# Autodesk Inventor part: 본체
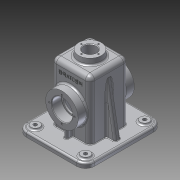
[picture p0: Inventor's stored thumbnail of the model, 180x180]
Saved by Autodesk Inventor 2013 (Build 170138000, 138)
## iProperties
Created: 2016-01
Part Number: 본체
Material: 알루미늄 6061
Document SubType Name: Modeling
Designer: User
Density: 2.71 g/cm^3
Mass: 804.864 g
Surface Area: 910.184 cm^2
Volume: 296.998 cm^3
Author: User
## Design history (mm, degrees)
sketch "스케치1"
  geometry: L1 (-32.5, -55)-(32.5, -55); L2 (32.5, -55)-(32.5, 55); L3 (32.5, 55)-(-32.5, 55); L4 (-32.5, 55)-(-32.5, -55); L5 (-32.5, -55)-(32.5, 55); L6 (32.5, -55)-(-32.5, 55); 1 further point
  constraints: 12 end point, 2 midpoint, 2 parallel, 1 horizontal, 1 perpendicular
  dimensions: "d0" = 65 distance of L2.end L3.end; "d2" = 110 distance of L1.end L2.end
extrude "돌출1" new body sketch "스케치1" stored distance "d3" = 65; taper "d4" = 0 deg
feature "쉘1" dims "d5" = 5
sketch "스케치2"
  geometry: L1 (-32.5, -55)-(-32.5, 55) reference; L2 (-32.5, 55)-(32.5, 55) reference; L3 (32.5, 55)-(32.5, -55) reference; L4 (32.5, -55)-(27.5, -55) reference; L5 (27.5, -55)-(27.5, 50) reference; L6 (27.5, 50)-(-27.5, 50) reference; L7 (-27.5, 50)-(-27.5, -55) reference; L8 (-27.5, -55)-(-32.5, -55) reference; L9 (32.5, 27.5)-(47.5, 27.5); L10 (47.5, 27.5)-(47.5, 0); L11 (75.884, 0)-(-75.884, 0); L12 (32.5, 27.5)-(32.5, 0); L13 (32.5, 0)-(47.5, 0); 2 further points
  constraints: 10 end point, 3 perpendicular, 2 midpoint, 2 point on line, 1 coincident, 1 parallel
  dimensions: "d6" = 55 diameter of L9 L11; "d8" = 15 distance of L9.start L9.end
revolve "회전1" sketch "스케치2" stored, may be unused: angle "d9" = 90 deg
hole "구멍1" diameter "d12" = 30; stored, may be unused: countersink angle "d16" = 90 deg, drill point angle "d18" = 118 deg; dims "d10" = 10, "d11" = 10, "d13" = 6, "d14" = 35, "d15" = 17, "d17" = 8
sketch "스케치3"
  geometry: L1 (84.363, 0)-(-84.363, 0); L2 (65, 20)-(55, 20); L3 (55, 20)-(55, 0); L4 (55, 0)-(65, 0); L5 (65, 0)-(65, 20); L6 (65, 20)-(55, 0); L7 (55, 20)-(65, 0); L8 (55, -32.5)-(-55, -32.5) reference; L9 (-55, -32.5)-(-55, -27.5) reference; L10 (-55, -27.5)-(50, -27.5) reference; L11 (50, -27.5)-(50, 27.5) reference; L12 (50, 27.5)-(-55, 27.5) reference; L13 (-55, 27.5)-(-55, 32.5) reference; L14 (-55, 32.5)-(55, 32.5) reference; L15 (55, 32.5)-(55, -32.5) reference; 3 further points
  constraints: 14 end point, 3 midpoint, 2 horizontal, 2 parallel, 1 coincident, 1 perpendicular, 1 point on line
  dimensions: "d19" = 40 diameter of L2 L1; "d21" = 10 distance between parallel lines of L15 L5; "d22" = 10 distance of L3.end L4.end
revolve "회전2" sketch "스케치3" stored, may be unused: angle "d23" = 90 deg
hole "구멍2" diameter "d26" = 21; stored, may be unused: countersink angle "d30" = 90 deg, drill point angle "d32" = 118 deg; dims "d24" = 10, "d25" = 10, "d27" = 6, "d28" = 4, "d29" = 2, "d31" = 8
sketch "스케치4"
  geometry: L1 (65, -65)-(65, 0) reference; L2 (0, 0)-(65, 0) reference; L3 (0, 0)-(0, -65) reference; L4 (65, -65)-(0, -65) reference; L5 (-27.5, -85)-(92.5, -85); L6 (92.5, -85)-(92.5, 20); L7 (92.5, 20)-(-27.5, 20); L8 (-27.5, 20)-(-27.5, -85); L9 (-27.5, -85)-(92.5, 20); L10 (92.5, -85)-(-27.5, 20); L11 (5, -60)-(60, -60); L12 (60, -60)-(60, -5); L13 (60, -5)-(5, -5); L14 (5, -5)-(5, -60); L15 (5, -60)-(60, -5); L16 (60, -60)-(5, -5); 1 further point
  constraints: 24 end point, 4 midpoint, 4 parallel, 2 horizontal, 2 perpendicular
  dimensions: "d33" = 120 distance of L6.end L7.end; "d35" = 105 distance of L5.end L6.end
extrude "돌출2" join sketch "스케치4" distance "d36" = 2; taper "d37" = 0 deg
sketch "스케치5"
  geometry: L1 (-32.5, -25)-(97.5, -25); L2 (97.5, -25)-(97.5, 90); L3 (97.5, 90)-(-32.5, 90); L4 (-32.5, 90)-(-32.5, -25); L5 (-32.5, -25)-(97.5, 90); L6 (97.5, -25)-(-32.5, 90); L7 (0, 0)-(65, 0); L8 (65, 0)-(65, 65); L9 (65, 65)-(0, 65); L10 (0, 65)-(0, 0); L11 (0, 0)-(65, 65); L12 (65, 0)-(0, 65); 1 further point
  constraints: 24 end point, 4 midpoint, 4 parallel, 2 horizontal, 2 perpendicular
  dimensions: "d38" = 130 distance of L3.end L2.end; "d39" = 115 distance of L2.end L1.end
extrude "돌출3" join sketch "스케치5" distance "d40" = 8; taper "d41" = 0 deg
sketch "스케치6"
  geometry: L1 (-42.5, -27.5)-(-42.5, -45); L2 (-27.5, 15)-(-30.5, 15) reference; L3 (-30.5, 15)-(-30.5, 17.5) reference; L4 (-30.5, 17.5)-(-47.5, 17.5) reference; L5 (-47.5, 17.5)-(-47.5, 27.5) reference; L6 (-47.5, 27.5)-(-32.5, 27.5) reference; L7 (-32.5, 27.5)-(-32.5, 55) reference; L8 (-32.5, 55)-(-20, 55) reference; L9 (-20, 55)-(-20, 65) reference; L10 (-20, 65)-(-10.5, 65) reference; L11 (-10.5, 65)-(-10.5, 50) reference; L12 (-10.5, 50)-(-27.5, 50) reference; L13 (-27.5, 50)-(-27.5, 15) reference; L14 (-30.5, -15)-(-27.5, -15) reference; L15 (-27.5, -15)-(-27.5, -55) reference; L16 (-27.5, -55)-(-60, -55) reference; L17 (-60, -55)-(-60, -53) reference; L18 (-60, -53)-(-65, -53) reference; L19 (-65, -53)-(-65, -45) reference; L20 (-65, -45)-(-32.5, -45) reference; L21 (-32.5, -45)-(-32.5, -27.5) reference; L22 (-32.5, -27.5)-(-47.5, -27.5) reference; L23 (-47.5, -27.5)-(-47.5, -17.5) reference; L24 (-47.5, -17.5)-(-30.5, -17.5) reference; L25 (-30.5, -17.5)-(-30.5, -15) reference; L26 (30.5, 15)-(27.5, 15) reference; L27 (27.5, 15)-(27.5, 50) reference; L28 (27.5, 50)-(10.5, 50) reference; L29 (10.5, 50)-(10.5, 65) reference; L30 (10.5, 65)-(20, 65) reference; L31 (20, 65)-(20, 55) reference; L32 (20, 55)-(32.5, 55) reference; L33 (32.5, 55)-(32.5, 27.5) reference; L34 (32.5, 27.5)-(47.5, 27.5) reference; L35 (47.5, 27.5)-(47.5, 17.5) reference; L36 (47.5, 17.5)-(30.5, 17.5) reference; L37 (30.5, 17.5)-(30.5, 15) reference; L38 (27.5, -15)-(30.5, -15) reference; L39 (30.5, -15)-(30.5, -17.5) reference; L40 (30.5, -17.5)-(47.5, -17.5) reference; L41 (47.5, -17.5)-(47.5, -27.5) reference; L42 (47.5, -27.5)-(32.5, -27.5) reference; L43 (32.5, -27.5)-(32.5, -45) reference; L44 (32.5, -45)-(65, -45) reference; L45 (65, -45)-(65, -53) reference; L46 (65, -53)-(60, -53) reference; L47 (60, -53)-(60, -55) reference; L48 (60, -55)-(27.5, -55) reference; L49 (27.5, -55)-(27.5, -15) reference; 1 further point
  constraints: 2 end point, 2 point on line, 1 parallel, 1 vertical
  dimensions: "d42" = 15 distance between parallel lines of L1 L15
feature "리브1" sketch "스케치6" dims "d43" = 1, "d44" = 6, "d45" = 0, "d46" = 0, "d47" = 1, "d48" = 1
sketch "스케치7"
  geometry: L1 (40.069, -32.5)-(-45, -47.5); L2 (-53, -57.5)-(-45, -57.5) reference; L3 (-45, -57.5)-(-45, 57.5) reference; L4 (-45, -32.5)-(55, -32.5) reference; 1 further point
  constraints: 2 end point, 2 point on line
  dimensions: "d49" = 10 distance from line of L2 L1.end; "d50" = 10 deg angle of L2 L1
feature "리브2" sketch "스케치7" dims "d51" = 1, "d52" = 10, "d53" = 0, "d54" = 0, "d55" = 1, "d56" = 1
sketch "스케치8"
  geometry: C1 r 7.5 at (-17.5, 75); 1 further point
  constraints: 1 centre point
  dimensions: "d57" = 15 diameter of C1; "d58" = 50 horizontal distance of point (32.5, 32.5) C1.centre; "d59" = 42.5 vertical distance of point (32.5, 32.5) C1.centre
extrude "돌출4" join sketch "스케치8" distance "d60" = 3; taper "d61" = 0 deg
sketch "스케치9"
  geometry: C1 r 7.5 at (0, 0) reference; C2 r 3 at (0, 0); 1 further point
  constraints: 1 centre point, 1 coincident
  dimensions: "d62" = 6 diameter of C2
extrude "돌출5" cut sketch "스케치9" distance "d64" = 40; taper "d65" = 0 deg
fillet "모깎기1" dims "d66" = 10
fillet "모깎기2" dims "d67" = 15
fillet "모깎기3" dims "d68" = 3
fillet "모깎기4" dims "d75" = 8
fillet "모깎기5" dims "d76" = 8
sketch "스케치10"
  geometry: C1 r 20 at (0, 0) reference; 1 further point
  constraints: 1 vertical alignment
  dimensions: "d77" = 14.5 distance of C1.centre point (0, 14.5)
hole "구멍3" sketch "스케치10" at (0, 14.5) diameter "d78" = 2.459; stored, may be unused: countersink angle "d82" = 90 deg, drill point angle "d84" = 118 deg; dims "d79" = 7, "d80" = 3.6, "d81" = 2, "d83" = 9
sketch "스케치11"
  geometry: C1 r 17.5 at (0, 0) reference; 1 further point
  constraints: 1 vertical alignment
  dimensions: "d88" = 21 distance of C1.centre point (0, 21)
hole "구멍4" sketch "스케치11" at (0, 21) diameter "d89" = 3.242; stored, may be unused: countersink angle "d93" = 90 deg, drill point angle "d95" = 118 deg; dims "d90" = 8, "d91" = 3.6, "d92" = 2, "d94" = 10
fillet "모깎기6" dims "d99" = 3
fillet "모깎기7" dims "d100" = 3
fillet "모깎기8" dims "d101" = 3
fillet "모깎기9" dims "d102" = 3
fillet "모깎기10" dims "d103" = 3
fillet "모깎기11" dims "d104" = 3
fillet "모깎기12" dims "d105" = 3
fillet "모깎기13" dims "d106" = 3
fillet "모깎기14" dims "d107" = 1
fillet "모깎기15" dims "d108" = 3
fillet "모깎기16" dims "d109" = 3
chamfer "모따기1" distance "d110" = 1; stored, may be unused: second distance "d111" = 2, angle "d112" = 45 deg
fillet "모깎기17" dims "d113" = 0.3
chamfer "모따기2" distance "d114" = 1; stored, may be unused: second distance "d115" = 2, angle "d116" = 45 deg
sketch "스케치12"
  geometry: L1 (44.5, 18)-(4.5, 18) reference; L2 (-8, 0)-(-8, -91) reference; 1 further point
  constraints: 1 other
  dimensions: "d117" = 26 distance from line of L1 point (24.5, -8); "d118" = 32.5 distance from line of L2 point (24.5, -8)
feature "엠보싱1" sketch "스케치12" dims "d6" = 55, "d8" = 15, "d119" = 0.5, "d120" = 0
feature "면 기울기1" dims angle "d121" = 5 deg
fillet "모깎기18" dims "d122" = 3
node "솔리드1"
mirror "대칭1"
mirror "대칭2"
mirror "대칭3"
pattern_linear "직사각형 패턴1" dims "d74" = 85
pattern_circular "원형 패턴1" dims angle "d86" = 360 deg
pattern_circular "원형 패턴2" dims angle "d97" = 360 deg
mirror "대칭4"
node "절단 모서리 투영1"
node "절단 모서리 투영2"
node "절단 모서리 투영3"
